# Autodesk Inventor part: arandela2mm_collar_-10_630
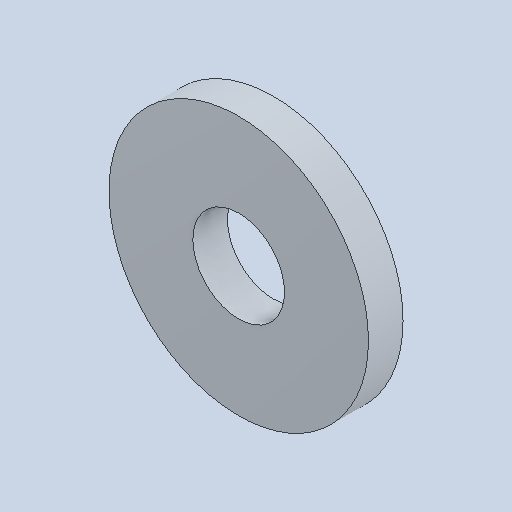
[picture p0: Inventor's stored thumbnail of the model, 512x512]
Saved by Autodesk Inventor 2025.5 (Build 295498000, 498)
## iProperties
Created: 2026-10
Part Number: arandela2mm_collar_-10_630
Material: Genérico
Document SubType Name: Modeling
Designer: Luis M
Density: 1 g/cm^3
Appearance: Valor por defecto
Author: Luis M
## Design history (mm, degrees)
feature "Base1"
node "Sólido1"
